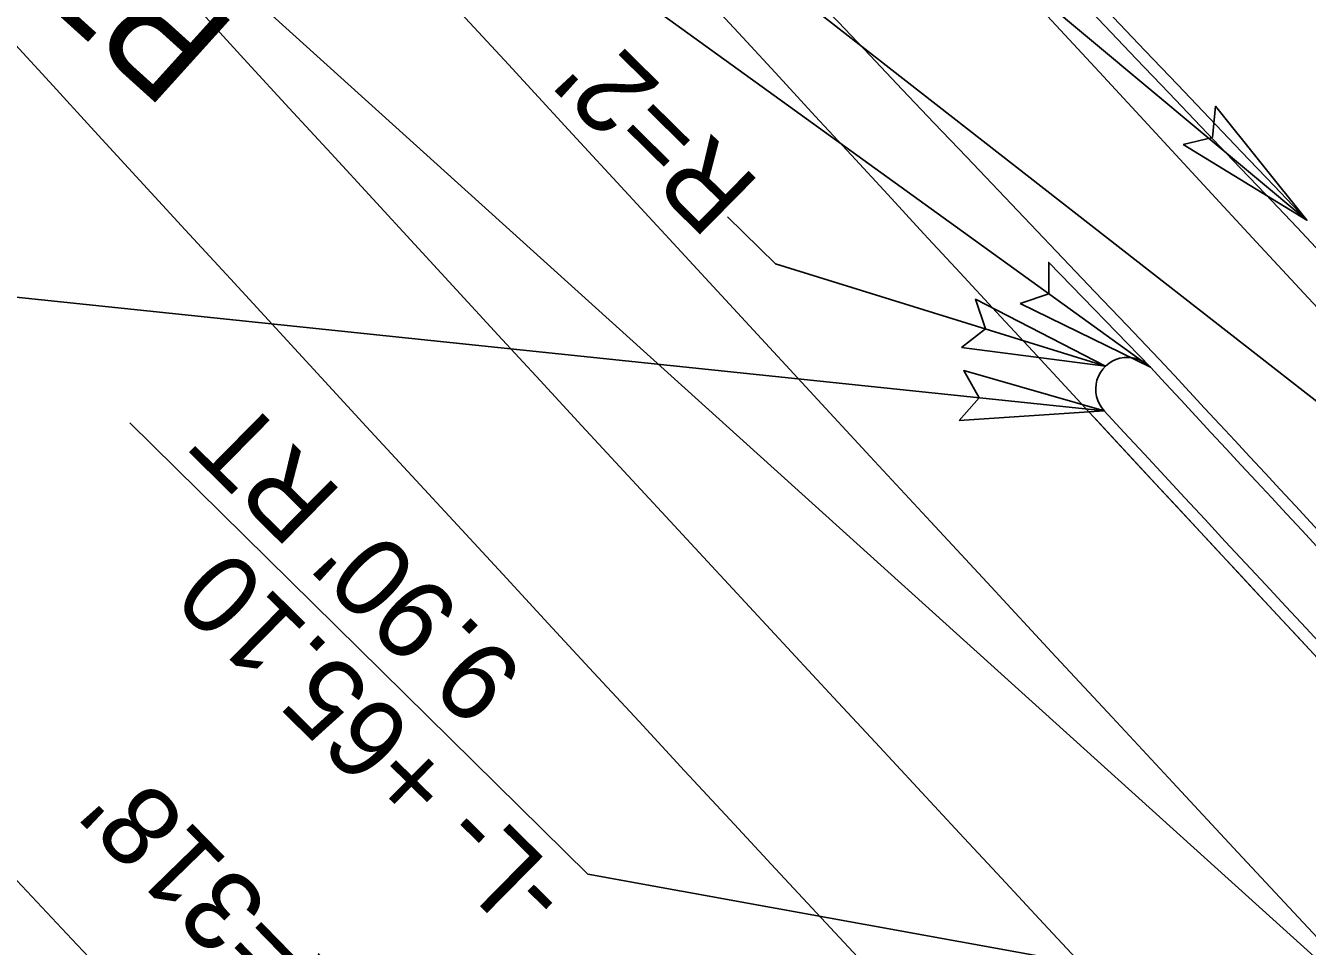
# Model space of a CAD drawing. Extents: x 1262642 to 1268358, y 767825 to 773481.
# Drawn here: x 1266608.5 to 1266689.1, y 772227.9 to 772285.8 of the extents above; entities that cross this region are included whole.
import ezdxf

# ---------------------------------------------------------------- set-up
doc = ezdxf.new("R2010")
doc.units = 0
for name, color, linetype in [('Prop Conc 1ft 6in Curb and Gutter', 7, 'Continuous'), ('Prop Conc 5in Monolithic Keyed In Island', 7, 'Continuous'), ('Prop Dimension', 7, 'Continuous'), ('Prop Dimension Text', 7, 'Continuous'), ('Prop EOT', 7, 'Continuous'), ('Prop Horizontal Alignment', 7, 'Continuous'), ('Prop Horizontal Alignment Station Label', 7, 'Continuous'), ('Prop Lane Lines', 7, 'Continuous'), ('Prop Paved Shoulder', 7, 'Continuous'), ('Prop Shade Light', 7, 'Continuous'), ('Prop Shade Medium', 7, 'Continuous'), ('Prop Terminator CELL', 7, 'Continuous'), ('Scratch_Level_3', 7, 'Continuous')]:
    doc.layers.add(name, color=color, linetype=linetype)

msp = doc.modelspace()

# ---------------------------------------------------------------- linework, layer by layer
at = {"layer": 'Prop Conc 1ft 6in Curb and Gutter'}
for centre, radius, start, end in [((1275047.307, 780021.225), 11385.75, 220.9464115, 223.1036607), ((1274932.678, 780143.08), 11396.75, 221.7861987, 223.6697938)]:
    msp.add_arc(centre, radius, start, end, dxfattribs=at)
at = {"layer": 'Prop Conc 5in Monolithic Keyed In Island'}
for centre, radius, start, end in [((1266677.831, 772262.919), 2, 43.56827, 223.56827), ((1275047.307, 780021.225), 11410.25, 222.8296601, 223.2792706), ((1275047.307, 780021.225), 11414.25, 222.8297896, 223.4298287)]:
    msp.add_arc(centre, radius, start, end, dxfattribs=at)
at = {"layer": 'Prop Dimension Text'}
for p, q in [((1266588.483, 772357.653), (1266689.117, 772273.543)), ((1266602.443, 772319.807), (1266679.28, 772264.297)), ((1266637.674, 772302.797), (1266726.388, 772233.528)), ((1266652.679, 772273.759), (1266655.688, 772270.794)), ((1266590.659, 772270.505), (1266676.364, 772261.559)), ((1266615.074, 772260.796), (1266643.887, 772232.407)), ((1266755.582, 772212.148), (1266643.887, 772232.407))]:
    msp.add_line(p, q, dxfattribs=at)
msp.add_lwpolyline([(1266655.688, 772270.794), (1266676.452, 772264.368)], dxfattribs=at)
at = {"layer": 'Prop EOT'}
for centre, radius, start, end in [((1275047.307, 780021.225), 11439, 220.5050908, 222.9935866), ((1275047.307, 780021.225), 11385, 220.9464115, 222.9935866), ((1274932.678, 780143.08), 11397.5, 221.7859832, 223.6697938), ((1275047.307, 780021.225), 11397.5, 222.8287756, 223.1041206), ((1275047.307, 780021.225), 11409.5, 222.8296601, 223.2792706), ((1275047.307, 780021.225), 11415, 222.8297896, 223.4298287)]:
    msp.add_arc(centre, radius, start, end, dxfattribs=at)
at = {"layer": 'Prop Horizontal Alignment'}
msp.add_arc((1275047.307, 780021.225), 11400, 216.7663646, 222.9935866, dxfattribs=at)
at = {"layer": 'Prop Horizontal Alignment Station Label'}
msp.add_line((1266769.823, 772154.715), (1266566.881, 772338.064), dxfattribs=at)
at = {"layer": 'Prop Lane Lines'}
for centre, radius, start, end in [((1275047.307, 780021.225), 11373, 216.3649439, 223.1327476), ((1275047.307, 780021.225), 11427, 216.3674993, 223.5476842), ((1275047.307, 780021.225), 11415, 220.9464115, 223.1041206), ((1274932.678, 780143.08), 11409.5, 221.7861987, 223.6697938)]:
    msp.add_arc(centre, radius, start, end, dxfattribs=at)
at = {"layer": 'Prop Paved Shoulder'}
msp.add_line((1266468.355, 772380.5), (1266611.433, 772228.315), dxfattribs=at)
for centre, radius, start, end in [((1275047.307, 780021.225), 11449, 220.5050908, 223.2024475), ((1266840.27, 772443.458), 314.091, 223.23333, 241.33253)]:
    msp.add_arc(centre, radius, start, end, dxfattribs=at)
at = {"layer": 'Prop Shade Light'}
msp.add_line((1266611.433, 772228.315), (1266468.355, 772380.5), dxfattribs=at)
for centre, radius, start, end in [((1275047.307, 780021.225), 11439, 220.5050908, 222.9935866), ((1275047.307, 780021.225), 11449, 220.5050908, 223.2024475), ((1266840.27, 772443.458), 314.091, 223.23333, 241.33253)]:
    msp.add_arc(centre, radius, start, end, dxfattribs=at)
at = {"layer": 'Prop Shade Medium'}
for centre, radius, start, end in [((1266677.831, 772262.919), 2, 43.56827, 223.56827), ((1275047.307, 780021.225), 11410.25, 222.8296601, 223.2792706), ((1275047.307, 780021.225), 11414.25, 222.8297896, 223.4298287)]:
    msp.add_arc(centre, radius, start, end, dxfattribs=at)
at = {"layer": 'Prop Terminator CELL'}
for points in [[(1266681.331, 772278.317), (1266689.117, 772273.543), (1266683.372, 772280.717), (1266683.181, 772278.756)], [(1266671.077, 772268.311), (1266679.28, 772264.297), (1266672.881, 772270.894), (1266672.876, 772268.923)], [(1266667.396, 772265.548), (1266676.452, 772264.368), (1266668.28, 772268.572), (1266668.905, 772266.704)], [(1266667.252, 772260.952), (1266676.364, 772261.559), (1266667.529, 772264.09), (1266668.507, 772262.379)]]:
    msp.add_lwpolyline(points, close=True, dxfattribs=at)
at = {"layer": 'Scratch_Level_3'}
msp.add_arc((1271970.399, 777276.391), 7371.864, 222.9672513, 223.6138945, dxfattribs=at)

# ---------------------------------------------------------------- texts
at = {"layer": 'Prop Dimension'}
for s, rotation, p in [("R=2'", 135.42387, (1266654.838, 772275.832)), ("R=318'", 134.2575, (1266630.079, 772224.229))]:
    msp.add_text(s, height=5, rotation=rotation, dxfattribs=at).set_placement(p)
at = {"layer": 'Prop Dimension Text'}
for s, p in [("9.90' RT", (1266640.046, 772245.028)), ('-L- +65.10', (1266643.025, 772231.564))]:
    msp.add_text(s, height=5, rotation=135.42387, dxfattribs=at).set_placement(p)
at = {"layer": 'Prop Horizontal Alignment Station Label'}
msp.add_text('PT Sta.  18+18.75', height=7, rotation=137.90382, dxfattribs=at).set_placement((1266621.929, 772285.635))

doc.saveas('drawing.dxf')
